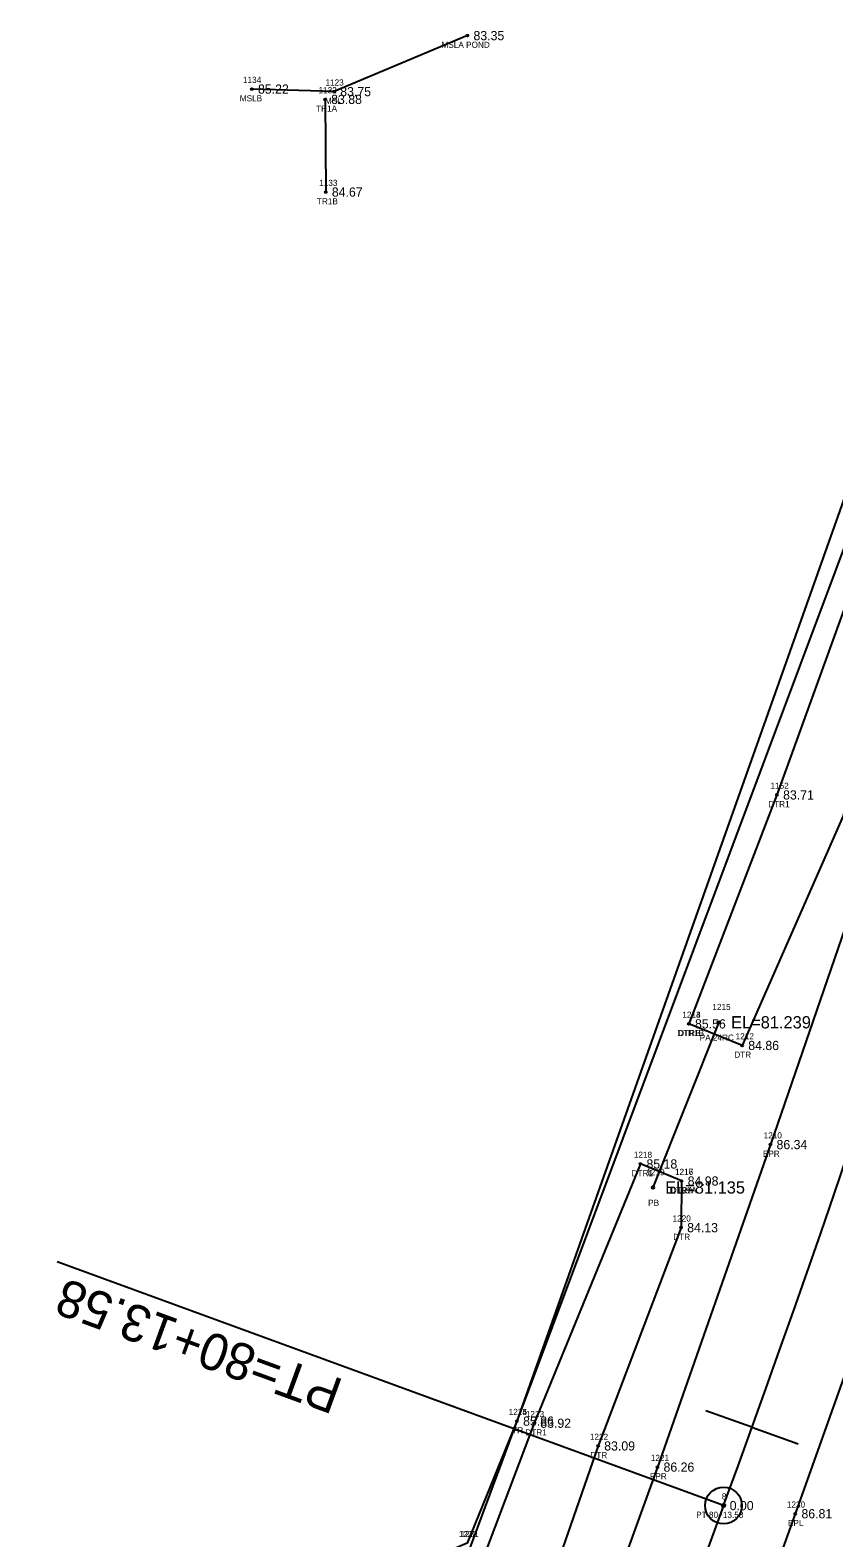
# Model space of a CAD drawing. Extents: x 2139392 to 2143384, y 505395 to 510520.
# Drawn here: x 2141220.5 to 2141351.5, y 510076.4 to 510322.4 of the extents above; entities that cross this region are included whole.
import ezdxf

# ---------------------------------------------------------------- set-up
doc = ezdxf.new("R2010")
doc.units = 0
for name, color, linetype in [('RD_EX_DR_Pipe', 7, 'Continuous'), ('RD_EX_DR_Pipe_txCode', 7, 'Continuous'), ('RD_EX_Fence_Other', 7, 'Continuous'), ('RD_EX_Fence_Other_txCode', 7, 'Continuous'), ('RD_EX_H2O', 7, 'Continuous'), ('RD_EX_H2O_txCode', 7, 'Continuous'), ('RD_EX_Misc_txCode', 7, 'Continuous'), ('RD_EX_Road', 7, 'Continuous'), ('RD_EX_Road_txCode', 7, 'Continuous'), ('RD_EX_TX_Fence_Other_ELEV', 7, 'Continuous'), ('RD_EX_TX_H2O_ELEV', 7, 'Continuous'), ('RD_EX_TX_Misc_ELEV', 7, 'Continuous'), ('RD_EX_TX_Road_ELEV', 7, 'Continuous'), ('RD_EX_TX_VEG_ELEV', 7, 'Continuous'), ('RD_EX_VEG', 7, 'Continuous'), ('RD_EX_VEG_txCode', 7, 'Continuous'), ('RD_HC_Cl', 7, 'Continuous'), ('RD_HC_Data', 7, 'Continuous'), ('RD_HC_Data_Tic', 7, 'Continuous'), ('RD_HC_Survey_ELEV', 7, 'Continuous'), ('RD_HC_txCode', 7, 'Continuous'), ('RD_SMD_Locator', 7, 'Continuous'), ('RD_TX_Pipe_ElevEX', 7, 'Continuous')]:
    doc.layers.add(name, color=color, linetype=linetype)

msp = doc.modelspace()

# ---------------------------------------------------------------- linework, layer by layer
at = {"layer": 'RD_EX_DR_Pipe'}
msp.add_line((2141332.76, 510160.53), (2141322.01, 510133.58), dxfattribs=at)
at = {"layer": 'RD_EX_Fence_Other'}
msp.add_lwpolyline([(2141372.32, 510299.98), (2141357.62, 510249.8), (2141299.84, 510095.47), (2141291.7, 510075.55), (2141249.56, 510057.46), (2141172.32, 510090.13)], dxfattribs=at)
at = {"layer": 'RD_EX_H2O'}
for points in [[(2141291.75, 510321.48), (2141270.02, 510312.34), (2141256.61, 510312.76)], [(2141365.7, 510240.33), (2141358.81, 510241.26), (2141357.05, 510238.63), (2141342.24, 510197.62), (2141327.87, 510160.27)], [(2141365.7, 510240.33), (2141363.12, 510236.72), (2141353.03, 510194.23), (2141336.56, 510156.75), (2141327.87, 510160.27)], [(2141326.68, 510134.64), (2141319.96, 510137.42), (2141302.64, 510095.13), (2141282.65, 510042.25), (2141266.05, 509995.54), (2141269.91, 509989.52)], [(2141326.68, 510134.64), (2141326.6, 510127.03), (2141313.07, 510091.42), (2141294.73, 510038.52), (2141280.37, 509991.45), (2141269.91, 509989.52)]]:
    msp.add_lwpolyline(points, dxfattribs=at)
at = {"layer": 'RD_EX_Road'}
for points in [[(2141389.23, 510293.58), (2141374.66, 510243.58), (2141359.1, 510192.72), (2141341.17, 510140.58), (2141322.74, 510087.97), (2141303.61, 510035.12), (2141287.18, 509990.16), (2141276.99, 509962.02), (2141248.91, 509884.35), (2141213.37, 509787.47), (2141207.76, 509772.94), (2141199.35, 509749.36), (2141191.47, 509727.8), (2141175.93, 509686.04), (2141140.09, 509588.3), (2141106.08, 509494.11), (2141096.82, 509469.24), (2141063.82, 509378.98), (2141052.52, 509348.48), (2141043.48, 509323.88)], [(2141412.62, 510288.46), (2141398.29, 510238.16), (2141381.65, 510185.39), (2141379.05, 510176.51), (2141367.08, 510141.57), (2141363.58, 510131.95), (2141345.23, 510080.36), (2141326.05, 510027.03), (2141308.64, 509979.4), (2141271.24, 509876.37), (2141240, 509789.51), (2141233.78, 509773.43), (2141223.56, 509746.41), (2141212.18, 509714.93), (2141204.36, 509694.36), (2141197.99, 509676.56), (2141193.66, 509664.6), (2141161.61, 509577.24), (2141123.75, 509473.61), (2141115.5, 509450.65), (2141102.09, 509414.61), (2141086.27, 509371.27), (2141050.42, 509272.83)]]:
    msp.add_lwpolyline(points, dxfattribs=at)
at = {"layer": 'RD_EX_VEG'}
msp.add_line((2141268.54, 510311.08), (2141268.65, 510295.96), dxfattribs=at)
msp.add_lwpolyline([(2141372.32, 510299.98), (2141299.84, 510095.47), (2141264.54, 510000.34)], dxfattribs=at)
at = {"layer": 'RD_HC_Cl'}
msp.add_line((2141333.53, 510081.69), (2140670.51, 508268.37), dxfattribs=at)
msp.add_arc((2138642.96, 511065.46), 2864.78, 339.91581, 348.5415, dxfattribs=at)
at = {"layer": 'RD_HC_Data'}
msp.add_line((2141333.53, 510081.69), (2141224.85, 510121.43), dxfattribs=at)
for radius in [3, 0.282]:
    msp.add_circle((2141333.53, 510081.69), radius, dxfattribs=at)
at = {"layer": 'RD_HC_Data_Tic'}
for q in [(2141330.64, 510097.17), (2141345.69, 510091.75)]:
    msp.add_line((2141338.16, 510094.46), q, dxfattribs=at)
at = {"layer": 'RD_SMD_Locator'}
for centre, radius in [((2141291.75, 510321.48), 0.15), ((2141256.61, 510312.76), 0.15), ((2141270.02, 510312.34), 0.15), ((2141268.54, 510311.08), 0.15), ((2141268.65, 510295.96), 0.15), ((2141342.24, 510197.62), 0.15), ((2141327.87, 510160.27), 0.15), ((2141327.87, 510160.27), 0.15), ((2141332.76, 510160.53), 0.2), ((2141336.56, 510156.75), 0.15), ((2141341.17, 510140.58), 0.15), ((2141319.96, 510137.42), 0.15), ((2141326.68, 510134.64), 0.15), ((2141326.68, 510134.64), 0.15), ((2141322.01, 510133.58), 0.2), ((2141326.6, 510127.03), 0.15), ((2141299.84, 510095.47), 0.15), ((2141299.84, 510095.47), 0.15), ((2141302.64, 510095.13), 0.15), ((2141313.07, 510091.42), 0.15), ((2141322.74, 510087.97), 0.15), ((2141333.53, 510081.69), 0.15), ((2141345.23, 510080.36), 0.15)]:
    msp.add_circle(centre, radius, dxfattribs=at)

# ---------------------------------------------------------------- texts
at = {"layer": 'RD_EX_DR_Pipe_txCode'}
for s, p in [('1215', (2141331.7, 510162.53)), ('PA 24RC', (2141329.64, 510157.53)), ('1219', (2141320.95, 510135.58)), ('PB', (2141321.23, 510130.58))]:
    msp.add_text(s, height=1, dxfattribs=at).set_placement(p)
at = {"layer": 'RD_EX_Fence_Other_txCode'}
for s, p in [('1224', (2141298.49, 510096.47)), ('FR', (2141299.09, 510093.47)), ('1232', (2141290.36, 510076.55)), ('1231', (2141290.64, 510076.55))]:
    msp.add_text(s, height=1, dxfattribs=at).set_placement(p)
at = {"layer": 'RD_EX_H2O_txCode'}
for s, p in [('1152', (2141341.18, 510198.62)), ('DTR1', (2141340.81, 510195.62)), ('1213', (2141326.81, 510161.27)), ('1214', (2141326.81, 510161.27)), ('DTR1B', (2141325.97, 510158.27)), ('DTRB', (2141326.13, 510158.27)), ('1212', (2141335.5, 510157.75)), ('DTR', (2141335.29, 510154.75)), ('1218', (2141318.9, 510138.42)), ('DTR1', (2141318.53, 510135.42)), ('1216', (2141325.6, 510135.64)), ('1217', (2141325.62, 510135.64)), ('DTR1A', (2141324.76, 510132.64)), ('DTRA', (2141324.93, 510132.64)), ('1220', (2141325.22, 510128.03)), ('DTR', (2141325.33, 510125.03)), ('1223', (2141301.29, 510096.13)), ('DTR1', (2141301.21, 510093.13)), ('1222', (2141311.73, 510092.42)), ('DTR', (2141311.81, 510089.42))]:
    msp.add_text(s, height=1, dxfattribs=at).set_placement(p)
at = {"layer": 'RD_EX_Misc_txCode'}
for s, p in [('MSLA POND', (2141287.53, 510319.48)), ('1134', (2141255.16, 510313.76)), ('1123', (2141268.61, 510313.34)), ('MSLB', (2141254.64, 510310.76)), ('MSL', (2141268.52, 510310.34))]:
    msp.add_text(s, height=1, dxfattribs=at).set_placement(p)
at = {"layer": 'RD_EX_Road_txCode'}
for s, p in [('1210', (2141340.07, 510141.58)), ('EPR', (2141339.94, 510138.58)), ('1221', (2141321.67, 510088.97)), ('EPR', (2141321.51, 510085.97)), ('1230', (2141343.85, 510081.36)), ('EPL', (2141344.03, 510078.36))]:
    msp.add_text(s, height=1, dxfattribs=at).set_placement(p)
at = {"layer": 'RD_EX_TX_Fence_Other_ELEV'}
msp.add_text('85.86', height=1.5, dxfattribs=at).set_placement((2141300.84, 510094.72))
at = {"layer": 'RD_EX_TX_H2O_ELEV'}
for s, p in [('83.71', (2141343.24, 510196.87)), ('85.56', (2141328.87, 510159.52)), ('85.56', (2141328.87, 510159.52)), ('84.86', (2141337.56, 510156)), ('85.18', (2141320.96, 510136.67)), ('84.98', (2141327.68, 510133.89)), ('84.98', (2141327.68, 510133.89)), ('84.13', (2141327.6, 510126.28)), ('83.92', (2141303.64, 510094.38)), ('83.09', (2141314.07, 510090.67))]:
    msp.add_text(s, height=1.5, dxfattribs=at).set_placement(p)
at = {"layer": 'RD_EX_TX_Misc_ELEV'}
for s, p in [('83.35', (2141292.75, 510320.73)), ('85.22', (2141257.61, 510312.01)), ('83.75', (2141271.02, 510311.59))]:
    msp.add_text(s, height=1.5, dxfattribs=at).set_placement(p)
at = {"layer": 'RD_EX_TX_Road_ELEV'}
for s, p in [('86.34', (2141342.17, 510139.83)), ('86.26', (2141323.74, 510087.22)), ('86.81', (2141346.23, 510079.61))]:
    msp.add_text(s, height=1.5, dxfattribs=at).set_placement(p)
at = {"layer": 'RD_EX_TX_VEG_ELEV'}
for s, p in [('83.88', (2141269.54, 510310.33)), ('84.67', (2141269.65, 510295.21)), ('85.86', (2141300.84, 510094.72))]:
    msp.add_text(s, height=1.5, dxfattribs=at).set_placement(p)
at = {"layer": 'RD_EX_VEG_txCode'}
for s, p in [('1132', (2141267.47, 510312.08)), ('TR1A', (2141267.09, 510309.08)), ('1133', (2141267.59, 510296.96)), ('TR1B', (2141267.22, 510293.96)), ('1225', (2141298.49, 510096.47)), ('TR', (2141299.05, 510093.47))]:
    msp.add_text(s, height=1, dxfattribs=at).set_placement(p)
at = {"layer": 'RD_HC_Data'}
msp.add_text('PT=80+13.58', height=6, rotation=159.9158, dxfattribs=at).set_placement((2141271.8, 510102.14))
at = {"layer": 'RD_HC_Survey_ELEV'}
msp.add_text('0.00', height=1.5, dxfattribs=at).set_placement((2141334.53, 510080.94))
at = {"layer": 'RD_HC_txCode'}
for s, p in [('8', (2141333.25, 510082.69)), ('PT 80+13.58', (2141329.07, 510079.69))]:
    msp.add_text(s, height=1, dxfattribs=at).set_placement(p)
at = {"layer": 'RD_TX_Pipe_ElevEX'}
for s, p in [('EL=81.239', (2141334.76, 510159.53)), ('EL=81.135', (2141324.01, 510132.58))]:
    msp.add_text(s, height=2, dxfattribs=at).set_placement(p)

doc.saveas('drawing.dxf')
